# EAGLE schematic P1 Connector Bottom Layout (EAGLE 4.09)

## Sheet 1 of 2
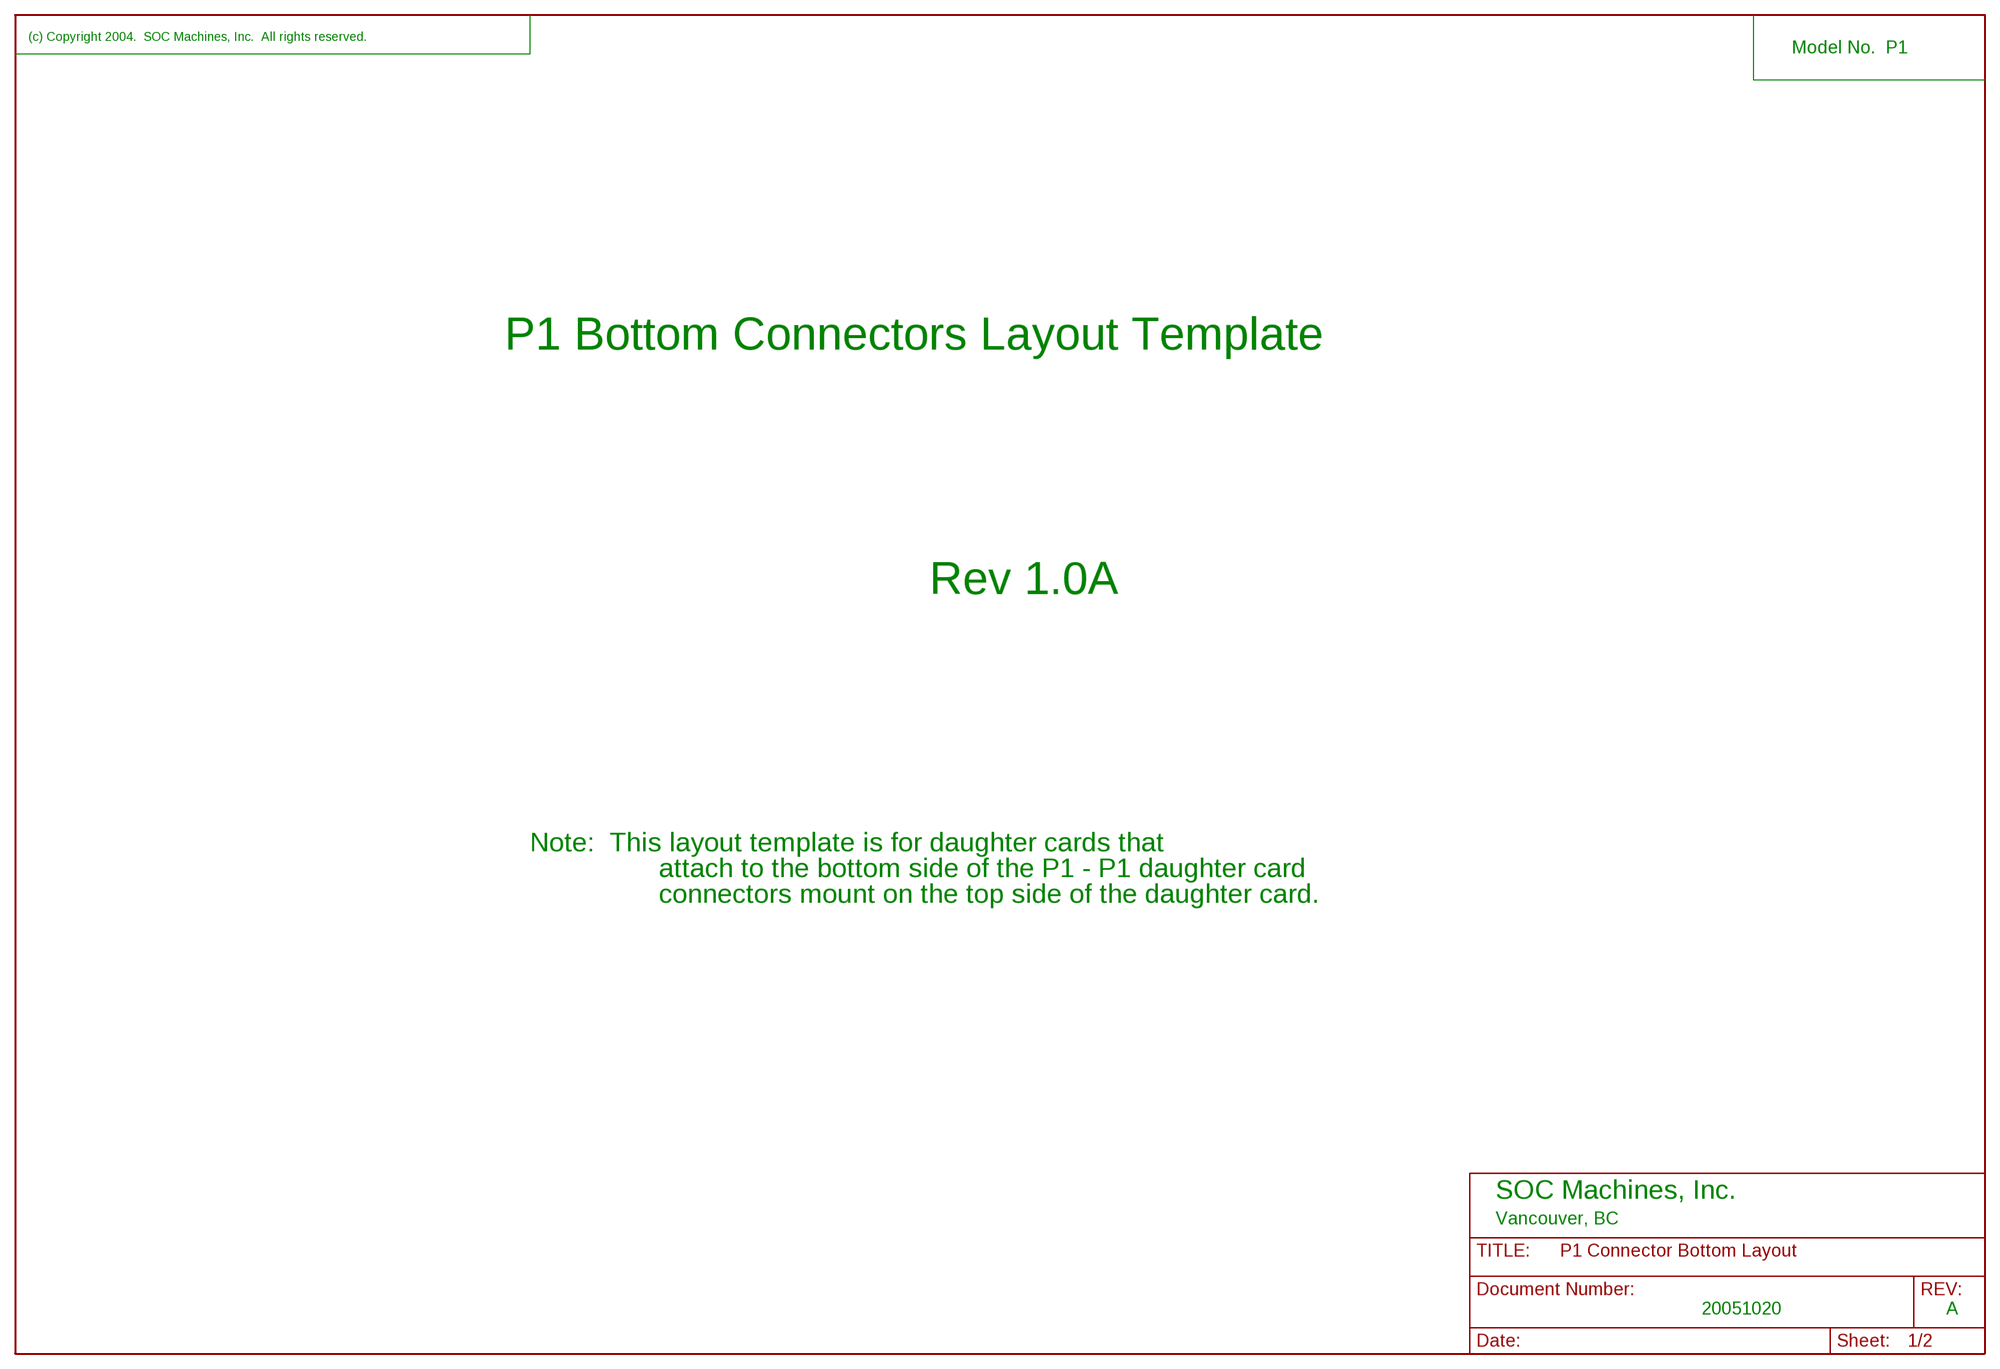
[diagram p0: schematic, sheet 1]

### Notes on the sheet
- (c) Copyright 2004.  SOC Machines, Inc.  All rights reserved.
- Model No.  P1
- P1 Bottom Connectors Layout Template
- Rev 1.0A
- Note:  This layout template is for daughter cards that
- attach to the bottom side of the P1 - P1 daughter card
- connectors mount on the top side of the daughter card.
- SOC Machines, Inc.
- Vancouver, BC
- 20051020 | A

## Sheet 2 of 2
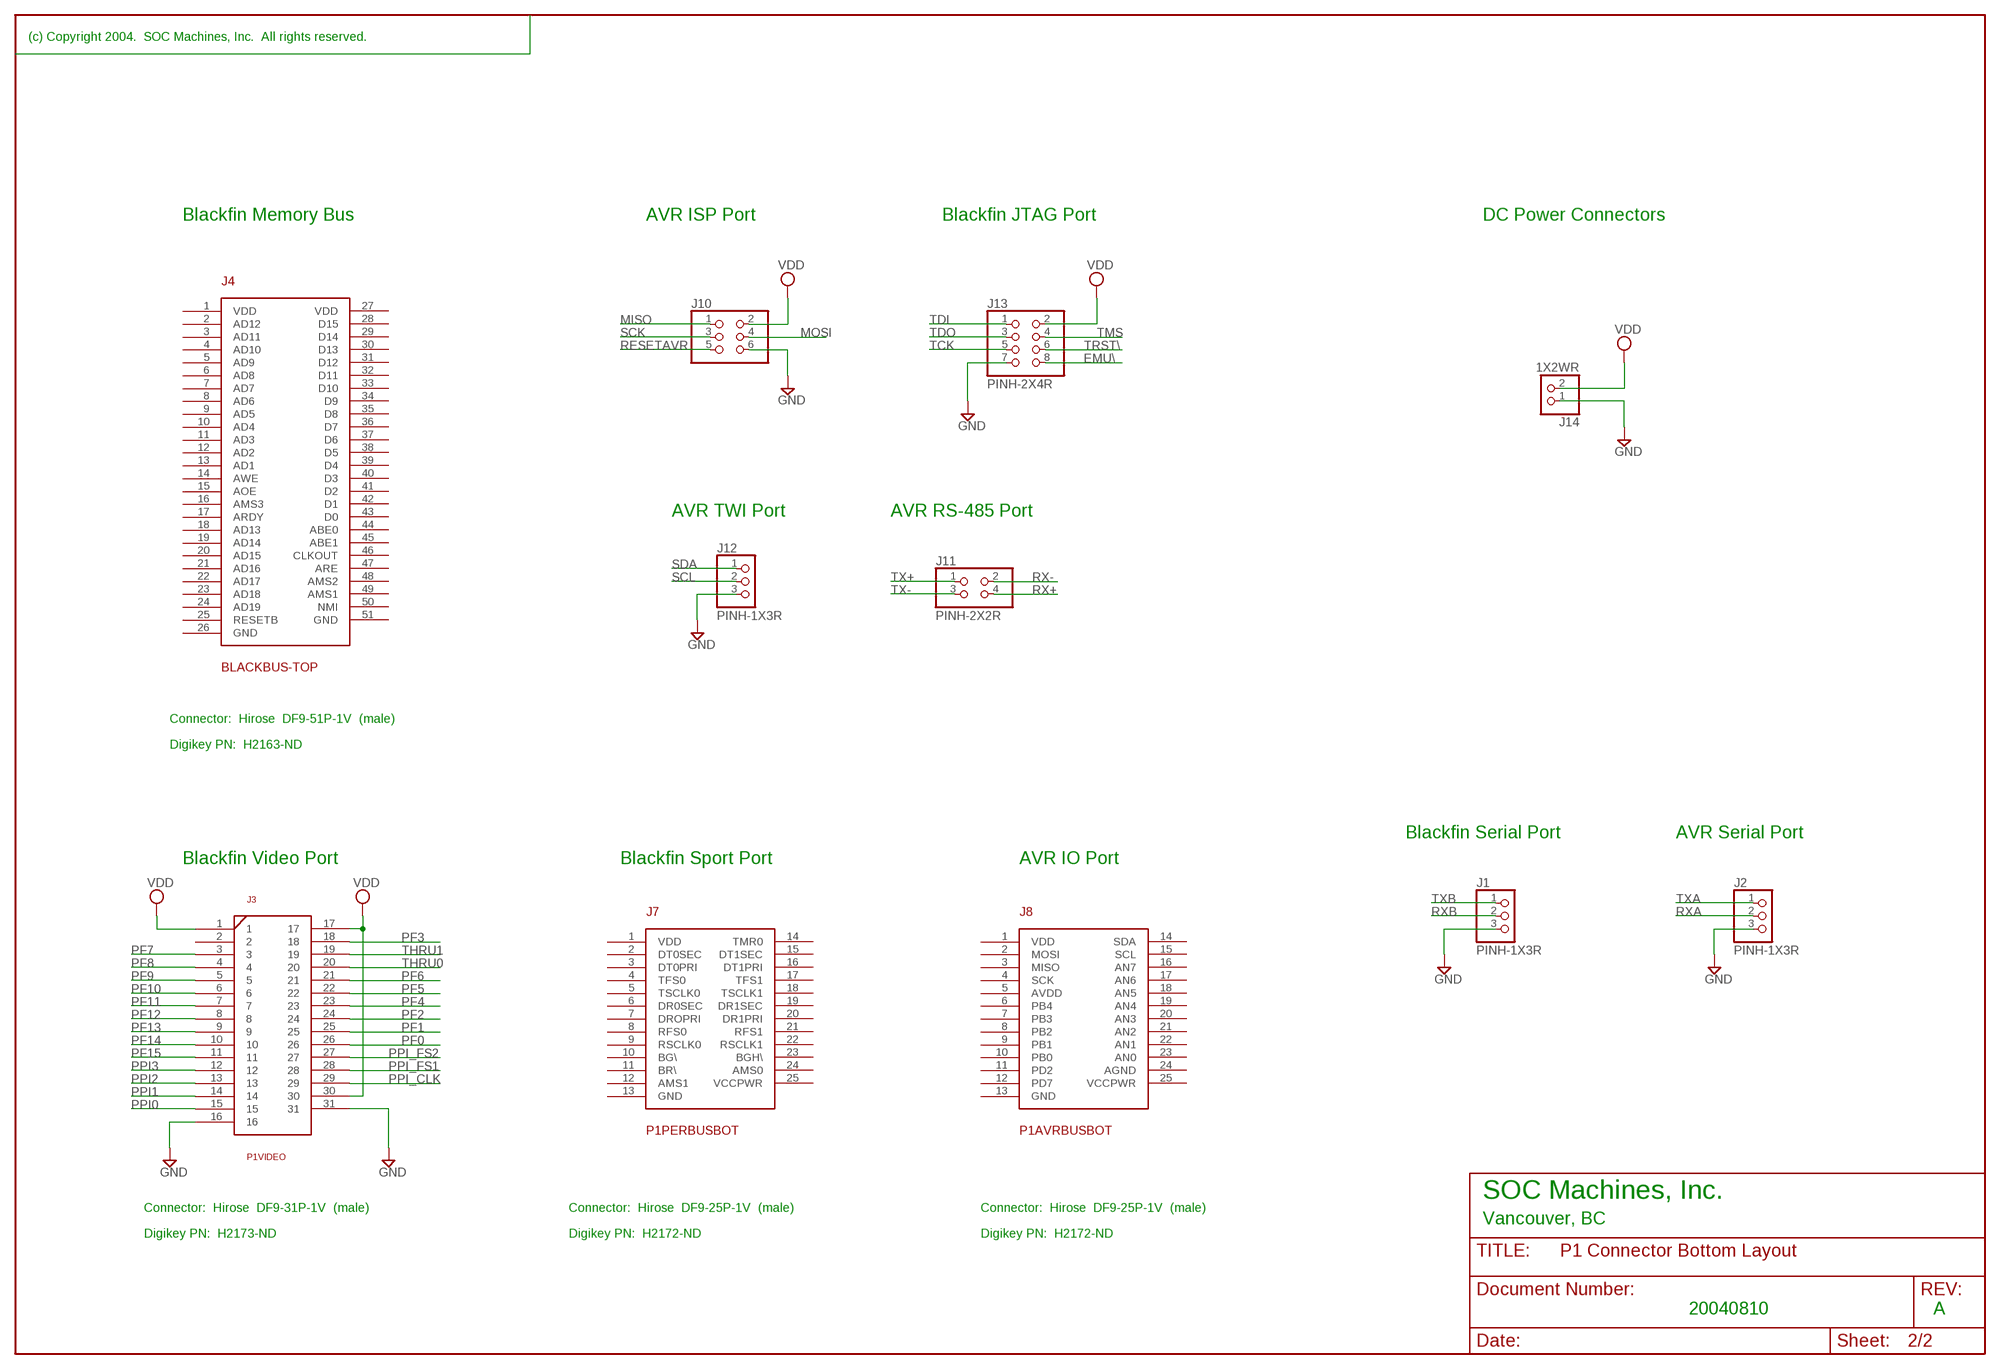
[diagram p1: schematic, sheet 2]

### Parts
J1  PINH-1X3R  [1X3ROUND]
J2  PINH-1X3R  [1X3ROUND]
J3  P1VIDEO  [DF9-31-TOP]
J4  BLACKBUS-TOP  BLACKBUS-TOPTOP  [DF9B-51P-1V]
J7  P1PERBUSBOT  [DF9-25SBOT]
J8  P1AVRBUSBOT  [DF9-25SBOT]
J10  PINHD-2X3  [2X03]
J11  PINH-2X2R  [2X2ROUND]
J12  PINH-1X3R  [1X3ROUND]
J13  PINH-2X4R  [2X4ROUND]
J14  1X2WR  [1X2WROUND]

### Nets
EMU\: J13.8
GND: J1.3 J2.3 J3.16 J3.31 J10.6 J12.3 J13.7 J14.1
MISO: J10.1
MOSI: J10.4
PF0: J3.26
PF1: J3.25
PF2: J3.24
PF3: J3.18
PF4: J3.23
PF5: J3.22
PF6: J3.21
PF7: J3.3
PF8: J3.4
PF9: J3.5
PF10: J3.6
PF11: J3.7
PF12: J3.8
PF13: J3.9
PF14: J3.10
PF15: J3.11
PPI0: J3.15
PPI1: J3.14
PPI2: J3.13
PPI3: J3.12
PPI_CLK: J3.29
PPI_FS1: J3.28
PPI_FS2: J3.27
RESETAVR: J10.5
RX+: J11.4
RX-: J11.2
RXA: J2.2
RXB: J1.2
SCK: J10.3
SCL: J12.2
SDA: J12.1
TCK: J13.5
TDI: J13.1
TDO: J13.3
THRU0: J3.20
THRU1: J3.19
TMS: J13.4
TRST\: J13.6
TX+: J11.1
TX-: J11.3
TXA: J2.1
TXB: J1.1
VDD: J3.1 J3.17 J3.30 J10.2 J13.2 J14.2
Unconnected: J3.2 J4.2(AD12) J4.3(AD11) J4.4(AD10) J4.5(AD9) J4.6(AD8) J4.7(AD7) J4.8(AD6) J4.9(AD5) J4.10(AD4) J4.11(AD3) J4.12(AD2) J4.13(AD1) J4.14(AWE) J4.15(AOE) J4.16(AMS3) J4.17(ARDY) J4.18(AD13) J4.19(AD14) J4.20(AD15) J4.21(AD16) J4.22(AD17) J4.23(AD18) J4.24(AD19) J4.25(RESETB) J4.28(D15) J4.29(D14) J4.30(D13) J4.31(D12) J4.32(D11) J4.33(D10) J4.34(D9) J4.35(D8) J4.36(D7) J4.37(D6) J4.38(D5) J4.39(D4) J4.40(D3) J4.41(D2) J4.42(D1) J4.43(D0) J4.44(ABE0) J4.45(ABE1) J4.46(CLKOUT) J4.47(ARE) J4.48(AMS2) J4.49(AMS1) J4.50(NMI) J7.2(DT0SEC) J7.3(DT0PRI) J7.4(TFS0) J7.5(TSCLK0) J7.6(DR0SEC) J7.7(DROPRI) J7.8(RFS0) J7.9(RSCLK0) J7.10(BG\) J7.11(BR\) J7.12(AMS1) J7.14(TMR0) J7.15(DT1SEC) J7.16(DT1PRI) J7.17(TFS1) J7.18(TSCLK1) J7.19(DR1SEC) J7.20(DR1PRI) J7.21(RFS1) J7.22(RSCLK1) J7.23(BGH\) J7.24(AMS0) J8.2(MOSI) J8.3(MISO) J8.4(SCK) J8.6(PB4) J8.7(PB3) J8.8(PB2) J8.9(PB1) J8.10(PB0) J8.11(PD2) J8.12(PD7) J8.14(SDA) J8.15(SCL) J8.16(AN7) J8.17(AN6) J8.18(AN5) J8.19(AN4) J8.20(AN3) J8.21(AN2) J8.22(AN1) J8.23(AN0) J8.25(VCCPWR)

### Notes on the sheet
- (c) Copyright 2004.  SOC Machines, Inc.  All rights reserved.
- Blackfin Memory Bus | AVR ISP Port | Blackfin JTAG Port | DC Power Connectors
- AVR TWI Port | AVR RS-485 Port
- Connector:  Hirose  DF9-51P-1V  (male)
- Digikey PN:  H2163-ND
- Blackfin Serial Port | AVR Serial Port
- Blackfin Video Port | Blackfin Sport Port | AVR IO Port
- SOC Machines, Inc.
- Connector:  Hirose  DF9-31P-1V  (male) | Connector:  Hirose  DF9-25P-1V  (male) | Connector:  Hirose  DF9-25P-1V  (male)
- Vancouver, BC
- Digikey PN:  H2173-ND | Digikey PN:  H2172-ND | Digikey PN:  H2172-ND
- 20040810 | A

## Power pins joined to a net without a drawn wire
AGND: J8.24(AGND)
AVDD: J8.5(AVDD)
GND: J4.26(GND) J4.51(GND) J7.13(GND) J8.13(GND)
VCCPWR: J7.25(VCCPWR)
VDD: J4.1(VDD) J4.27(VDD) J7.1(VDD) J8.1(VDD)

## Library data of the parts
J1 J2 J12 = pinhead:PINH-1X3R: 1x3 Pin Head Round
J3 = con-TI DSK 2:P1VIDEO: P1 Bottom Video Connector - Hirose DF9-31
J4 = con-TI DSK:BLACKBUS-TOP: Blackfin Bus Expansion top connector Hirsose DF9
J7 = con-TI DSK 2:P1PERBUS: P1 Blackfin Peripheral SPORT Bus
J8 = con-TI DSK 2:P1AVRBUS: P1 AVR Expansion Bus DF9-25 Hirose 1mm Spacing
J10 = pinhead:PINHD-2X3: PIN HEADER
J11 = pinhead:PINH-2X2R: Pin Head Jumper 2x2 Round 0.1"
J13 = pinhead:PINH-2X4R
J14 = pinhead:1X2WR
